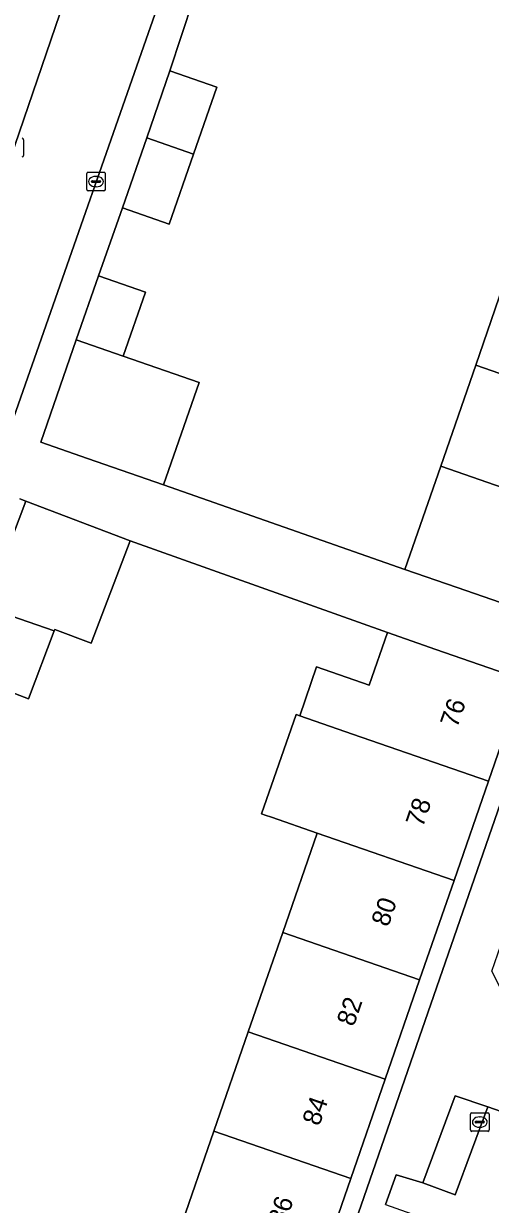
# Model space of a CAD drawing. Extents: x 160349 to 161355, y 381727 to 382854.
# Drawn here: x 160627.2 to 160652.4, y 382138.5 to 382202.2 of the extents above; entities that cross this region are included whole.
import ezdxf

# ---------------------------------------------------------------- set-up
doc = ezdxf.new("R2010")
doc.units = 0
for name, color, linetype in [('IMGEO_Erf', 7, 'Continuous'), ('IMGEO_Kolk', 7, 'Continuous'), ('IMGEO_Pand', 7, 'Continuous'), ('IMGEO_Pand_nummerreeks', 7, 'Continuous'), ('IMGEO_Parkeervlak_open', 7, 'Continuous'), ('IMGEO_Rijbaan_lokaal_open', 7, 'Continuous'), ('IMGEO_Rioolput', 7, 'Continuous'), ('IMGEO_Voetpad_open', 7, 'Continuous'), ('IMGEO_Woonerf_open', 7, 'Continuous')]:
    doc.layers.add(name, color=color, linetype=linetype)

msp = doc.modelspace()

# ---------------------------------------------------------------- linework, layer by layer
at = {"layer": 'IMGEO_Erf'}
for points in [[(160626.275, 382194.168), (160629.671, 382204.116), (160629.938, 382204.897), (160635.558, 382221.001), (160626.057, 382221.56)], [(160636.36, 382203.416), (160635.117, 382199.609), (160637.636, 382198.736), (160636.379, 382195.123), (160635.068, 382191.353), (160632.557, 382192.224), (160631.261, 382188.569), (160633.795, 382187.69), (160632.595, 382184.239), (160636.687, 382182.819), (160634.774, 382177.3), (160647.781, 382172.741), (160649.707, 382178.302), (160651.593, 382183.746), (160653.478, 382189.191), (160655.365, 382194.637), (160657.25, 382200.081), (160659.136, 382205.525)], [(160625.174, 382170.71), (160627.343, 382176.418), (160627.032, 382176.536)], [(160635.63, 382137.119), (160637.484, 382142.471), (160639.338, 382147.824), (160641.193, 382153.178), (160643.047, 382158.53), (160640.588, 382159.381), (160640.253, 382159.497), (160640.058, 382159.565), (160641.912, 382164.918), (160642.107, 382164.85), (160643.02, 382167.486), (160645.861, 382166.503), (160646.842, 382169.335), (160632.962, 382174.283), (160630.862, 382168.757), (160628.907, 382169.5), (160628.879, 382169.428), (160627.49, 382165.771), (160623.826, 382167.163)]]:
    msp.add_lwpolyline(points, dxfattribs=at)
msp.add_lwpolyline([(160655.119, 382166.468), (160654.174, 382166.795), (160652.281, 382161.329), (160650.426, 382155.975), (160648.573, 382150.623), (160646.719, 382145.27), (160644.864, 382139.917), (160643.011, 382134.564), (160641.156, 382129.211), (160639.302, 382123.858), (160637.448, 382118.505), (160635.594, 382113.151), (160633.702, 382107.689), (160634.64, 382107.343), (160634.794, 382107.787)], close=True, dxfattribs=at)
at = {"layer": 'IMGEO_Kolk'}
for p, q in [((160627.227, 382195.898), (160627.227, 382195.046)), ((160630.631, 382193.216), (160630.631, 382194.068)), ((160630.706, 382194.142), (160631.558, 382194.142)), ((160631.119, 382193.922), (160631.144, 382193.922)), ((160631.632, 382194.068), (160631.632, 382193.216)), ((160631.558, 382193.142), (160630.706, 382193.142)), ((160630.89, 382193.636), (160630.89, 382193.648)), ((160631.328, 382193.599), (160630.93, 382193.599)), ((160630.933, 382193.685), (160631.331, 382193.685)), ((160631.142, 382193.362), (160631.117, 382193.362)), ((160631.374, 382193.648), (160631.374, 382193.636))]:
    msp.add_line(p, q, dxfattribs=at)
for points in [[(160627.227, 382195.898), (160627.227, 382195.046)], [(160630.631, 382193.216), (160630.631, 382194.068)], [(160630.706, 382194.142), (160631.558, 382194.142)], [(160631.632, 382194.068), (160631.632, 382193.216)], [(160631.558, 382193.142), (160630.706, 382193.142)]]:
    msp.add_lwpolyline(points, dxfattribs=at)
for centre, radius, start, end in [((160627.151, 382195.896), 0.0765, 1.55205, 88.44795), ((160627.151, 382195.896), 0.0765, 1.55205, 88.44795), ((160627.151, 382195.048), 0.0765, 271.55205, 358.44795), ((160627.151, 382195.048), 0.0765, 271.55205, 358.44795), ((160630.708, 382194.066), 0.0765, 91.55205, 178.44795), ((160630.708, 382194.066), 0.0765, 91.55205, 178.44795), ((160631.556, 382194.066), 0.0765, 1.55205, 88.44795), ((160631.556, 382194.066), 0.0765, 1.55205, 88.44795), ((160630.708, 382193.218), 0.0765, 181.55205, 268.44795), ((160630.708, 382193.218), 0.0765, 181.55205, 268.44795), ((160630.93, 382193.645), 0.0403, 85.87752, 175.75265), ((160630.927, 382193.635), 0.0366, 178.93798, 274.71019), ((160631.331, 382193.642), 0.043, 264.86636, 352.45326), ((160631.335, 382193.647), 0.0386, 1.73085, 96.63898), ((160631.556, 382193.218), 0.0765, 271.55205, 358.44795), ((160631.556, 382193.218), 0.0765, 271.55205, 358.44795)]:
    msp.add_arc(centre, radius, start, end, dxfattribs=at)
for centre, major_axis, ratio, start_param, end_param in [((160631.118, 382193.642), (-0.387, 0.002), 0.722429, 4.712389, 7.853982), ((160631.143, 382193.642), (-0.39, 0.002), 0.717154, 1.570796, 4.712389)]:
    msp.add_ellipse(centre, major_axis=major_axis, ratio=ratio, start_param=start_param, end_param=end_param, dxfattribs=at)
at = {"layer": 'IMGEO_Pand'}
for points in [[(160633.864, 382195.996), (160636.379, 382195.123), (160637.636, 382198.736), (160635.117, 382199.609)], [(160633.864, 382195.996), (160632.557, 382192.224), (160635.068, 382191.353), (160636.379, 382195.123)], [(160653.478, 382189.191), (160651.593, 382183.746), (160659.139, 382181.129), (160661.024, 382186.573)], [(160630.064, 382185.117), (160632.595, 382184.239), (160633.795, 382187.69), (160631.261, 382188.569)], [(160630.064, 382185.117), (160628.15, 382179.595), (160630.675, 382178.72), (160634.774, 382177.3), (160636.687, 382182.819), (160632.595, 382184.239)], [(160659.139, 382181.129), (160651.593, 382183.746), (160649.707, 382178.302), (160657.253, 382175.684)], [(160657.253, 382175.684), (160649.707, 382178.302), (160647.781, 382172.741), (160650.604, 382171.763), (160655.328, 382170.127)], [(160628.879, 382169.428), (160628.907, 382169.5), (160630.862, 382168.757), (160632.962, 382174.283), (160627.343, 382176.418), (160625.174, 382170.71)], [(160628.879, 382169.428), (160625.174, 382170.71), (160623.826, 382167.163), (160627.49, 382165.771)], [(160654.174, 382166.795), (160649.45, 382168.432), (160646.842, 382169.335), (160645.861, 382166.503), (160643.02, 382167.486), (160642.107, 382164.85), (160644.948, 382163.867), (160652.281, 382161.329)], [(160652.281, 382161.329), (160644.948, 382163.867), (160642.107, 382164.85), (160641.912, 382164.918), (160640.058, 382159.565), (160640.253, 382159.497), (160640.588, 382159.381), (160643.047, 382158.53), (160650.426, 382155.975)], [(160641.193, 382153.178), (160648.573, 382150.623), (160650.426, 382155.975), (160643.047, 382158.53)], [(160646.719, 382145.27), (160648.573, 382150.623), (160641.193, 382153.178), (160639.338, 382147.824)], [(160646.719, 382145.27), (160639.338, 382147.824), (160637.484, 382142.471), (160644.864, 382139.917)], [(160644.864, 382139.917), (160637.484, 382142.471), (160635.63, 382137.119), (160643.011, 382134.564)]]:
    msp.add_lwpolyline(points, close=True, dxfattribs=at)
at = {"layer": 'IMGEO_Parkeervlak_open'}
msp.add_lwpolyline([(160652.241, 382143.773), (160650.485, 382144.361), (160648.749, 382139.677), (160650.485, 382139.034)], close=True, dxfattribs=at)
at = {"layer": 'IMGEO_Rijbaan_lokaal_open'}
msp.add_lwpolyline([(160574.045, 382225.164), (160574.354, 382225.146), (160598.291, 382223.527), (160598.324, 382223.525), (160620.253, 382221.901), (160626.057, 382221.56), (160635.558, 382221.001), (160629.938, 382204.897), (160629.671, 382204.116), (160626.275, 382194.168), (160624.387, 382188.463), (160623.792, 382187.389), (160622.316, 382182.98), (160619.935, 382176.513), (160624.54, 382174.828), (160649.821, 382247)], dxfattribs=at)
at = {"layer": 'IMGEO_Rioolput'}
for p, q in [((160651.315, 382142.53), (160651.315, 382143.382)), ((160651.39, 382143.456), (160652.242, 382143.456)), ((160651.574, 382142.95), (160651.574, 382142.962)), ((160652.012, 382142.913), (160651.614, 382142.913)), ((160651.617, 382142.999), (160652.015, 382142.999)), ((160651.803, 382143.236), (160651.828, 382143.236)), ((160652.058, 382142.962), (160652.058, 382142.95)), ((160652.316, 382143.382), (160652.316, 382142.53)), ((160652.242, 382142.456), (160651.39, 382142.456)), ((160651.826, 382142.676), (160651.801, 382142.676))]:
    msp.add_line(p, q, dxfattribs=at)
for points in [[(160651.315, 382142.53), (160651.315, 382143.382)], [(160651.39, 382143.456), (160652.242, 382143.456)], [(160652.316, 382143.382), (160652.316, 382142.53)], [(160652.242, 382142.456), (160651.39, 382142.456)]]:
    msp.add_lwpolyline(points, dxfattribs=at)
for centre, radius, start, end in [((160651.392, 382143.38), 0.0765, 91.55205, 178.44795), ((160651.392, 382143.38), 0.0765, 91.55205, 178.44795), ((160651.614, 382142.959), 0.0403, 85.87752, 175.75265), ((160651.611, 382142.949), 0.0366, 178.93798, 274.71019), ((160652.015, 382142.956), 0.043, 264.86636, 352.45326), ((160652.019, 382142.961), 0.0386, 1.73085, 96.63898), ((160652.24, 382143.38), 0.0765, 1.55205, 88.44795), ((160652.24, 382143.38), 0.0765, 1.55205, 88.44795), ((160651.392, 382142.532), 0.0765, 181.55205, 268.44795), ((160651.392, 382142.532), 0.0765, 181.55205, 268.44795), ((160652.24, 382142.532), 0.0765, 271.55205, 358.44795), ((160652.24, 382142.532), 0.0765, 271.55205, 358.44795)]:
    msp.add_arc(centre, radius, start, end, dxfattribs=at)
for centre, major_axis, ratio, start_param, end_param in [((160651.802, 382142.956), (-0.387, 0.002), 0.722429, 4.712389, 7.853982), ((160651.827, 382142.956), (-0.39, 0.002), 0.717154, 1.570796, 4.712389)]:
    msp.add_ellipse(centre, major_axis=major_axis, ratio=ratio, start_param=start_param, end_param=end_param, dxfattribs=at)
at = {"layer": 'IMGEO_Voetpad_open'}
for points in [[(160649.821, 382247), (160624.54, 382174.828), (160617.301, 382153.553), (160614.861, 382146.461), (160614.772, 382146.213), (160614.927, 382146.158), (160613.766, 382142.911), (160608.795, 382129.105)], [(160682.3, 382232.389), (160678.979, 382235.356), (160656.273, 382169.8), (160655.119, 382166.468), (160634.794, 382107.787), (160639.616, 382106.019), (160640.607, 382108.902), (160638.62, 382111.527), (160640.555, 382116.871), (160639.534, 382117.379), (160643.391, 382128.676)], [(160646.738, 382138.508), (160647.308, 382140.103), (160648.749, 382139.677), (160650.485, 382144.361), (160652.241, 382143.773), (160652.976, 382143.527), (160654.244, 382147.569), (160653.938, 382148.171), (160652.456, 382151.083), (160654.086, 382155.763), (160654.142, 382155.925), (160653.091, 382156.423), (160659.21, 382174.542), (160660.36, 382174.315), (160662.127, 382178.778), (160665.361, 382180.315), (160665.451, 382180.576), (160669.634, 382192.745), (160668.197, 382195.976), (160669.486, 382199.728), (160668.101, 382200.032), (160669.967, 382205.508)], [(160627.032, 382176.536), (160627.343, 382176.418), (160632.962, 382174.283), (160646.842, 382169.335), (160649.45, 382168.432), (160654.174, 382166.795), (160655.119, 382166.468), (160656.273, 382169.8), (160655.328, 382170.127), (160650.604, 382171.763), (160647.781, 382172.741), (160634.774, 382177.3), (160630.675, 382178.72), (160628.15, 382179.595), (160630.064, 382185.117), (160631.261, 382188.569), (160632.557, 382192.224), (160633.864, 382195.996), (160635.117, 382199.609), (160636.36, 382203.416)]]:
    msp.add_lwpolyline(points, dxfattribs=at)
at = {"layer": 'IMGEO_Woonerf_open'}
msp.add_lwpolyline([(160657.203, 382146.188), (160657.701, 382147.664), (160658.593, 382150.306), (160653.938, 382148.171), (160654.244, 382147.569), (160652.976, 382143.527), (160652.241, 382143.773), (160650.485, 382139.034), (160648.749, 382139.677), (160647.308, 382140.103), (160646.738, 382138.508), (160648.71, 382137.804), (160647.065, 382133.311), (160647.848, 382133.026), (160652.183, 382131.447)], close=True, dxfattribs=at)

# ---------------------------------------------------------------- texts
at = {"layer": 'IMGEO_Pand_nummerreeks'}
for s, rotation, p in [('76', 70.8978, (160650.594, 382164.157)), ('78', 70.8978, (160648.737, 382158.796)), ('80', 70.89592, (160646.879, 382153.43)), ('82', 70.89592, (160645.019, 382148.061)), ('84', 70.89592, (160643.162, 382142.698)), ('86', 70.89592, (160641.304, 382137.334))]:
    msp.add_text(s, height=1, rotation=rotation, dxfattribs=at).set_placement(p)

doc.saveas('drawing.dxf')
